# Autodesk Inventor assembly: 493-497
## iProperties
Author: Administrator
Shininess: 64.0
Angle Display Precision: 2
Document Length Units: 11272
Document Angle Units: 11286
Document Time Units: 11279
Document Mass Units: 11290
Document Length Units Precision: 3
Document Angle Units Precision: 2
Compacted: True
PropertySet Name: _Private Model Information
Created: 2002-03
Part Number: 493-497
Document SubType Name: Assembly
Designer: Administrator
Control State: 0
Master: False
Checked Out: False
PropertySet Name: Design Tracking Control
Density: 0.0
Volumn: 0.0
Area: 0.0
PropertySet Name: Model Information
